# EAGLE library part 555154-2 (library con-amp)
AMP connector
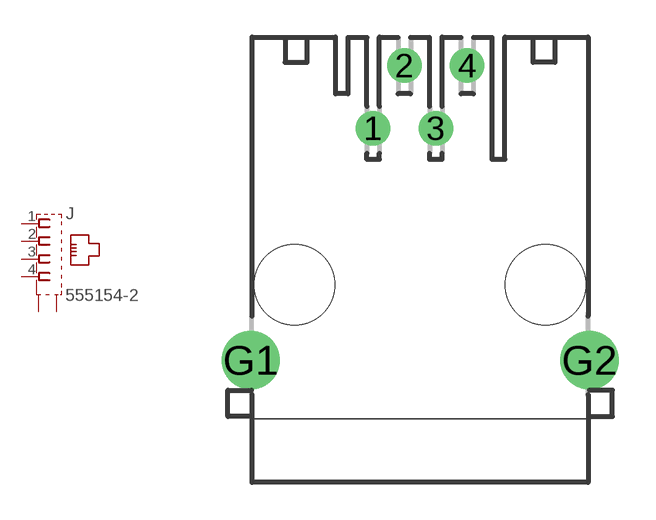
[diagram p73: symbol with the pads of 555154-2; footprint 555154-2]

Designator prefix J

## 555154-2 (MPN: 5555154-2; OC_FARNELL: 1558045; OC_NEWARK: 83K0906)  [555154-2]
1  1  pas
2  2  pas
3  3  pas
4  4  pas
G1  S2  pas
G2  S1  pas

## Footprint 555154-2 (pad centres in mm)
Modular Jack PC Board Ground
drill 0.889 round: 1 -1.905,6.35; 2 -0.635,8.89; 3 0.635,6.35; 4 1.905,8.89
drill 1.575 pad 2.184 round: G1 -6.858,-3.048; G2 6.858,-3.048
hole 3.251 at -5.08,0
hole 3.251 at 5.08,0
